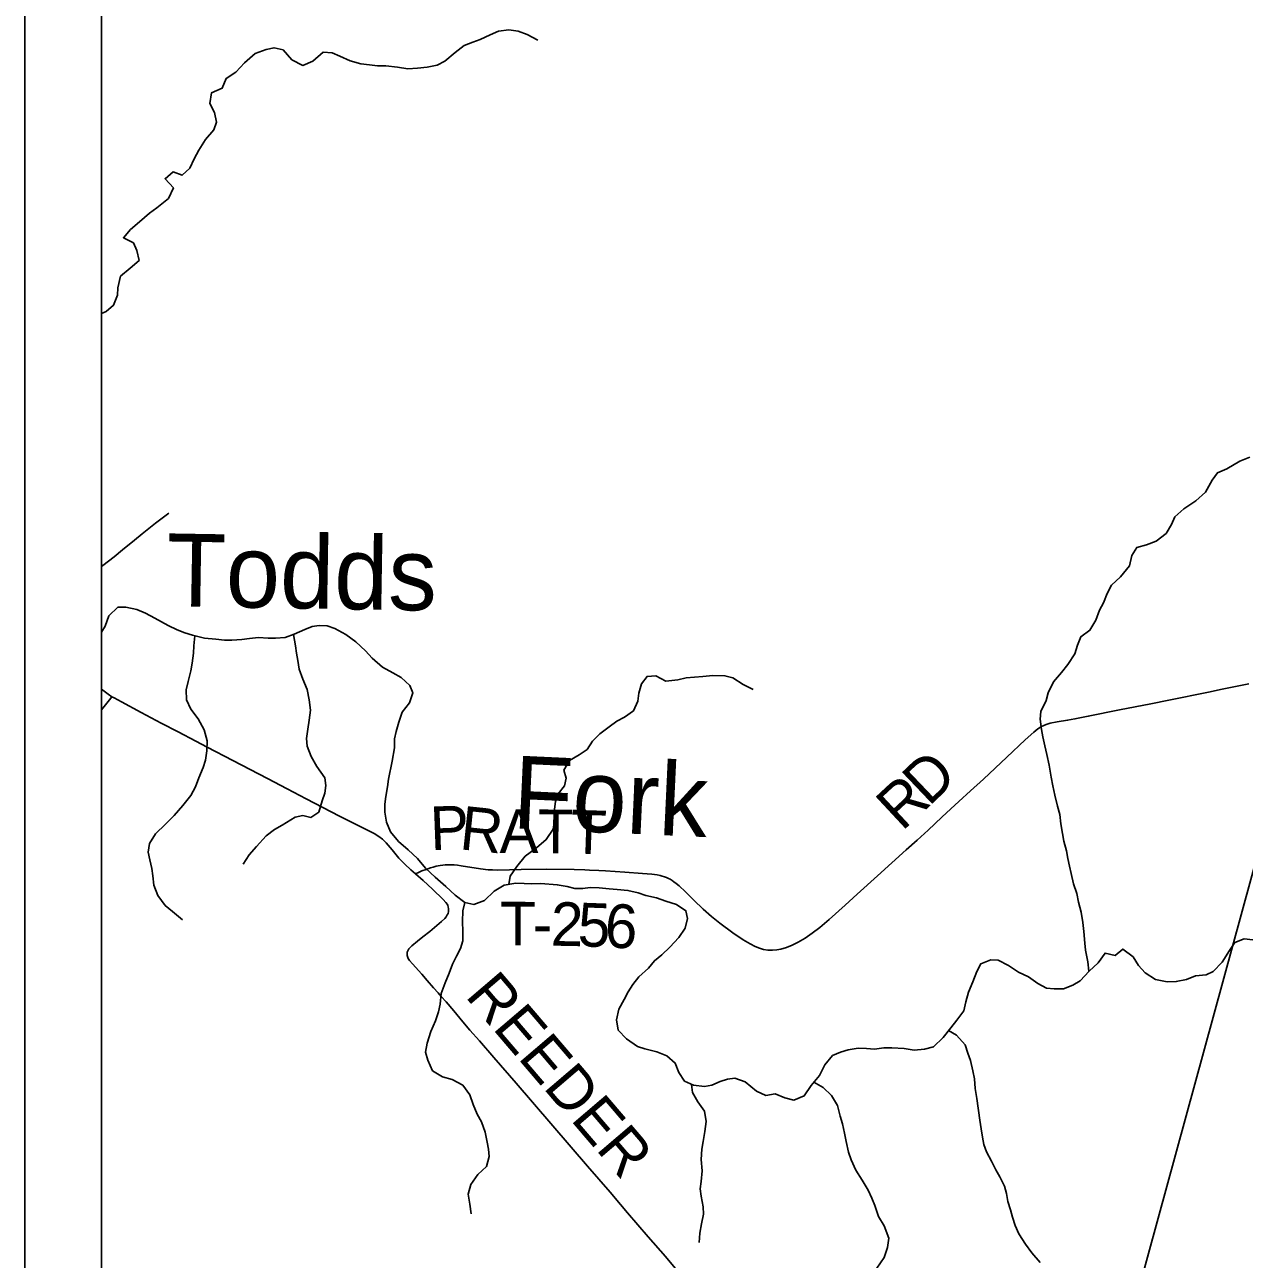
# Model space of a CAD drawing. Extents: x 0 to 34, y 0 to 22.
# Drawn here: x 2 to 3.586, y 15.761 to 17.368 of the extents above; entities that cross this region are included whole.
import ezdxf

# ---------------------------------------------------------------- set-up
doc = ezdxf.new("R2010")
doc.units = 0
for name, color, linetype in [('GM_X_Minor_River', 7, 'Continuous'), ('GM_X_Minor_River_Text', 7, 'Continuous'), ('GM_X_Township_Road', 7, 'Continuous'), ('GM_X_Township_Road_Text', 7, 'Continuous'), ('SH_Data', 7, 'Continuous')]:
    doc.layers.add(name, color=color, linetype=linetype)

msp = doc.modelspace()

# ---------------------------------------------------------------- linework, layer by layer
at = {"layer": 'GM_X_Minor_River'}
for points in [[(2.1, 16.9919), (2.1059, 16.9947), (2.1155, 17.0026), (2.1206, 17.0158), (2.1211, 17.0253), (2.1248, 17.0404), (2.137, 17.0509), (2.1489, 17.0609), (2.1457, 17.0739), (2.1413, 17.0838), (2.1285, 17.0905), (2.1378, 17.101), (2.1493, 17.1111), (2.1624, 17.1226), (2.1719, 17.1294), (2.1869, 17.1417), (2.1935, 17.1553), (2.1827, 17.1672), (2.1931, 17.1761), (2.2048, 17.1718), (2.2148, 17.1808), (2.2203, 17.1932), (2.2265, 17.2045), (2.235, 17.2181), (2.2462, 17.2308), (2.2494, 17.2407), (2.2469, 17.2536), (2.2406, 17.2651), (2.2431, 17.2791), (2.2569, 17.285), (2.262, 17.2978), (2.2746, 17.306), (2.2861, 17.318), (2.2996, 17.3303), (2.3141, 17.3355), (2.3244, 17.3376), (2.3361, 17.3348), (2.3476, 17.3221), (2.3619, 17.3147), (2.3749, 17.3202), (2.3883, 17.3318), (2.3997, 17.3309), (2.4099, 17.3269), (2.4234, 17.3207), (2.4374, 17.3167), (2.4484, 17.3154), (2.459, 17.3141), (2.4696, 17.314), (2.4848, 17.3123), (2.4984, 17.3102), (2.5109, 17.3111), (2.5234, 17.3125), (2.5367, 17.315), (2.5463, 17.3202), (2.5597, 17.3314), (2.5716, 17.3407), (2.5827, 17.3451), (2.5922, 17.3484), (2.6056, 17.3543), (2.6162, 17.3591), (2.6299, 17.3608), (2.642, 17.3591), (2.6537, 17.3548), (2.6673, 17.3474)], [(3.3843, 16.1362), (3.3828, 16.1486), (3.3799, 16.1634), (3.3789, 16.1729), (3.3776, 16.1878), (3.3763, 16.1996), (3.3742, 16.2129), (3.3706, 16.2262), (3.3685, 16.2372), (3.3641, 16.2498), (3.3613, 16.2632), (3.3588, 16.2727), (3.3567, 16.283), (3.3549, 16.2929), (3.3517, 16.3054), (3.3499, 16.3153), (3.3478, 16.3279), (3.3465, 16.34), (3.3432, 16.3511), (3.34, 16.3652), (3.3372, 16.3774), (3.3351, 16.3888), (3.3323, 16.4044), (3.3294, 16.4181), (3.3269, 16.4295), (3.3241, 16.4413), (3.3227, 16.4508), (3.321, 16.4642), (3.3215, 16.474), (3.3286, 16.4883), (3.3314, 16.4986), (3.338, 16.5129), (3.3484, 16.5249), (3.3569, 16.5354), (3.3658, 16.549), (3.3694, 16.5603), (3.3737, 16.5713), (3.3856, 16.5798), (3.393, 16.593), (3.3981, 16.6058), (3.4032, 16.6156), (3.4079, 16.6277), (3.4134, 16.6383), (3.4253, 16.6495), (3.4369, 16.6638), (3.4401, 16.677), (3.4467, 16.6876), (3.4589, 16.6908), (3.4715, 16.6956), (3.4845, 16.7056), (3.4915, 16.7173), (3.4958, 16.7275), (3.5077, 16.7376), (3.5234, 16.748), (3.5357, 16.7596), (3.5447, 16.7751), (3.5513, 16.7848), (3.5635, 16.79), (3.5803, 16.7996), (3.5936, 16.8048)], [(2.1, 16.5775), (2.1045, 16.5851), (2.1096, 16.5987), (2.1212, 16.6099), (2.1314, 16.6098), (2.1458, 16.6066), (2.1571, 16.6022), (2.1691, 16.5956), (2.1864, 16.5859), (2.1985, 16.5804), (2.2083, 16.5765), (2.2184, 16.5733), (2.2339, 16.5697), (2.2487, 16.5683), (2.2597, 16.5671), (2.2695, 16.5669), (2.2824, 16.5679), (2.2923, 16.5693), (2.3041, 16.5706), (2.3166, 16.5697), (2.3261, 16.5696), (2.3386, 16.5705), (2.3504, 16.5746), (2.3642, 16.5808), (2.3737, 16.5849), (2.3832, 16.5859), (2.3934, 16.5857), (2.4032, 16.5822), (2.4175, 16.5744), (2.4307, 16.5647), (2.4434, 16.5532), (2.452, 16.5436), (2.4654, 16.532), (2.479, 16.5242), (2.4895, 16.5184), (2.5011, 16.508), (2.5048, 16.4984), (2.5004, 16.4856), (2.4911, 16.4732), (2.4868, 16.4603), (2.4832, 16.4482), (2.4811, 16.4384), (2.481, 16.427), (2.4781, 16.4096), (2.4732, 16.3861), (2.4719, 16.3759), (2.4698, 16.3634), (2.4685, 16.3535), (2.4684, 16.3433), (2.4705, 16.3303), (2.4756, 16.3177), (2.486, 16.3051), (2.4988, 16.2943), (2.5107, 16.2827), (2.5215, 16.2704), (2.5339, 16.2585), (2.5477, 16.2465), (2.5601, 16.235), (2.5725, 16.2257), (2.5842, 16.2232), (2.5979, 16.228), (2.6106, 16.2404), (2.6236, 16.2481), (2.6388, 16.2506), (2.6498, 16.2504), (2.6596, 16.2499), (2.6714, 16.2505), (2.6926, 16.2487), (2.7055, 16.2463), (2.7157, 16.2439), (2.7259, 16.2437), (2.7354, 16.2451), (2.7472, 16.2449), (2.76, 16.2436), (2.7706, 16.2427), (2.7846, 16.2414), (2.7979, 16.2382), (2.8081, 16.2346), (2.8217, 16.2318), (2.8341, 16.2274), (2.8477, 16.2231), (2.8601, 16.2149), (2.8622, 16.205), (2.859, 16.1922), (2.8509, 16.1801), (2.8389, 16.1674), (2.8286, 16.1577), (2.819, 16.1498), (2.8112, 16.1401), (2.7989, 16.1288), (2.7908, 16.1191), (2.785, 16.1093)], [(2.2215, 16.5726), (2.2201, 16.5596), (2.2196, 16.5501), (2.2179, 16.5369), (2.2159, 16.527), (2.2126, 16.513), (2.2102, 16.5024), (2.2104, 16.4895), (2.2163, 16.4773), (2.2256, 16.4646), (2.2333, 16.4501), (2.2373, 16.436), (2.2367, 16.4231), (2.235, 16.411), (2.2323, 16.4011), (2.2267, 16.3876), (2.222, 16.3759), (2.2162, 16.3649), (2.2057, 16.3518), (2.1946, 16.3386), (2.183, 16.3274), (2.17, 16.3151), (2.1622, 16.3023), (2.1605, 16.2913), (2.1626, 16.281), (2.1655, 16.2699), (2.1665, 16.2601), (2.1678, 16.2483), (2.173, 16.2349), (2.1826, 16.2219), (2.1924, 16.2138), (2.2051, 16.203)], [(2.3498, 16.5744), (2.3521, 16.5597), (2.3535, 16.5498), (2.3552, 16.5403), (2.357, 16.5293), (2.3617, 16.5163), (2.3672, 16.5026), (2.37, 16.4893), (2.3717, 16.4759), (2.37, 16.4627), (2.3683, 16.4513), (2.3666, 16.4388), (2.3673, 16.4289), (2.3724, 16.4156), (2.3801, 16.4026), (2.3902, 16.388), (2.3915, 16.3777), (2.3903, 16.3679), (2.3871, 16.358), (2.3827, 16.3433), (2.372, 16.3362), (2.3618, 16.3386), (2.3519, 16.3365), (2.3347, 16.3261), (2.3247, 16.3205), (2.314, 16.3123), (2.3013, 16.2985), (2.292, 16.2876), (2.2843, 16.2755)], [(2.6295, 16.2491), (2.6314, 16.2598), (2.6399, 16.2726), (2.6511, 16.2857), (2.6656, 16.2969), (2.6783, 16.3074), (2.6872, 16.3209), (2.6897, 16.3346), (2.6891, 16.3471), (2.6904, 16.357), (2.694, 16.3668), (2.7021, 16.3773), (2.7041, 16.3875), (2.7012, 16.3978), (2.7086, 16.4102), (2.7212, 16.4177), (2.7316, 16.4247), (2.7386, 16.4353), (2.7482, 16.445), (2.7601, 16.454), (2.77, 16.4614), (2.78, 16.4666), (2.7918, 16.4748), (2.7977, 16.4876), (2.799, 16.4978), (2.8022, 16.5099), (2.8095, 16.5197), (2.8209, 16.5207), (2.8341, 16.5137), (2.8497, 16.5154), (2.8603, 16.5179), (2.8713, 16.5189), (2.882, 16.5195), (2.8949, 16.5208), (2.9108, 16.5206), (2.921, 16.5178), (2.9345, 16.5093), (2.9477, 16.5026)], [(2.5725, 16.2257), (2.57, 16.2147), (2.5695, 16.201), (2.57, 16.1878), (2.5698, 16.1756), (2.5667, 16.1658), (2.5616, 16.156), (2.5565, 16.1454), (2.5522, 16.1337), (2.5467, 16.1209), (2.5419, 16.1073), (2.5406, 16.0932), (2.5382, 16.0834), (2.5342, 16.0717), (2.5283, 16.0577), (2.5235, 16.0426), (2.5215, 16.0309), (2.5244, 16.0206), (2.5306, 16.0068), (2.5434, 15.9987), (2.5562, 15.9955), (2.5698, 15.9881), (2.5791, 15.9754), (2.5831, 15.9628), (2.5886, 15.9502), (2.5941, 15.9403), (2.5988, 15.9266), (2.6017, 15.914), (2.6034, 15.9045), (2.6041, 15.895), (2.6005, 15.8821), (2.5893, 15.8716), (2.5804, 15.8588), (2.5768, 15.846), (2.5789, 15.8331), (2.5806, 15.8205)], [(2.785, 16.1093), (2.7796, 16.0995), (2.7729, 16.0867), (2.7697, 16.073), (2.7718, 16.0597), (2.7826, 16.0482), (2.7969, 16.0381), (2.8067, 16.0353), (2.8222, 16.0313), (2.8354, 16.0262), (2.8462, 16.0166), (2.8506, 16.0044), (2.8584, 15.9933), (2.8701, 15.9878), (2.8841, 15.9864), (2.8936, 15.9878), (2.9046, 15.9926), (2.9142, 15.9959), (2.9237, 15.9969), (2.9369, 15.9922), (2.9519, 15.9802), (2.9639, 15.9744), (2.9761, 15.9765), (2.9885, 15.9714), (3.0002, 15.9685), (3.0139, 15.974), (3.0229, 15.9876), (3.0337, 16.0007), (3.0407, 16.0143), (3.0507, 16.0267), (3.061, 16.0307), (3.0709, 16.034), (3.0839, 16.0361), (3.0948, 16.0356), (3.1051, 16.0347), (3.1176, 16.0364), (3.1279, 16.0367), (3.1438, 16.0357), (3.157, 16.0336), (3.1703, 16.0346), (3.1821, 16.0378), (3.1948, 16.0498), (3.2044, 16.0626), (3.2126, 16.0727), (3.2214, 16.0847), (3.2239, 16.0965), (3.2275, 16.1089), (3.2334, 16.1225), (3.2385, 16.1358), (3.2436, 16.1456), (3.2565, 16.1511), (3.266, 16.1506), (3.2796, 16.1435), (3.2927, 16.135), (3.3055, 16.1288), (3.3179, 16.1202), (3.3292, 16.114), (3.339, 16.1131), (3.3512, 16.1133), (3.3634, 16.1181), (3.3729, 16.1237), (3.3845, 16.1364), (3.3964, 16.1473), (3.4053, 16.1597), (3.4185, 16.1568), (3.4285, 16.1651), (3.4416, 16.155), (3.4487, 16.1435), (3.4572, 16.1339), (3.4708, 16.1254), (3.4859, 16.1225), (3.4977, 16.1227), (3.511, 16.1256), (3.5228, 16.1304), (3.5365, 16.1317), (3.546, 16.1357), (3.5576, 16.1481), (3.5669, 16.1632), (3.5742, 16.1737), (3.5861, 16.1785), (3.5974, 16.1772)], [(3.2017, 16.059), (3.2119, 16.053), (3.2231, 16.0403), (3.2267, 16.0296), (3.23, 16.0201), (3.2332, 16.0064), (3.2353, 15.9961), (3.2363, 15.9835), (3.2384, 15.9706), (3.2425, 15.9425), (3.2442, 15.931), (3.246, 15.9204), (3.2474, 15.9109), (3.251, 15.9013), (3.2573, 15.8891), (3.2632, 15.878), (3.2684, 15.8685), (3.2743, 15.8566), (3.2768, 15.8471), (3.2789, 15.8368), (3.2821, 15.8258), (3.2847, 15.8162), (3.2883, 15.8052), (3.2931, 15.7945), (3.3016, 15.7811), (3.3098, 15.7696), (3.3206, 15.7573)], [(2.8674, 15.989), (2.8684, 15.9783), (2.8754, 15.9661), (2.8844, 15.9542), (2.8864, 15.9405), (2.8847, 15.9276), (2.8823, 15.9147), (2.8806, 15.9045), (2.88, 15.8912), (2.8813, 15.8764), (2.88, 15.8627), (2.8787, 15.8529), (2.8797, 15.8434), (2.8826, 15.8297), (2.8828, 15.8202), (2.8803, 15.8077), (2.8783, 15.7956), (2.8773, 15.7831)], [(3.0263, 15.9918), (3.0384, 15.9851), (3.0492, 15.9743), (3.057, 15.9613), (3.0606, 15.9476), (3.0635, 15.9377), (3.0663, 15.9255), (3.0684, 15.9145), (3.0717, 15.9008), (3.0749, 15.8908), (3.0812, 15.8775), (3.0893, 15.8644), (3.0971, 15.8514), (3.1019, 15.8411), (3.1059, 15.8312), (3.1106, 15.8171), (3.118, 15.8048), (3.1239, 15.7888), (3.1222, 15.7767), (3.1178, 15.7638), (3.1085, 15.7499)]]:
    msp.add_lwpolyline(points, dxfattribs=at)
at = {"layer": 'GM_X_Township_Road'}
for points in [[(3.7787, 17.0143), (3.7921, 17.074), (3.9903, 17.6899), (4.0744, 17.9948), (4.1901, 18.4135), (4.1943, 18.4289), (4.2897, 18.7747), (4.3389, 18.9527), (4.4789, 19.5742), (4.4849, 19.6021), (4.4654, 19.6041), (3.501, 19.6889), (3.4805, 19.8366), (3.1735, 19.8394), (3.1019, 19.912), (2.3144, 20.5665), (2.1, 20.7431), (2.1, 15.597), (2.2517, 15.5643), (3.1228, 15.3686), (3.3385, 15.3189), (3.6691, 16.5264), (3.7277, 16.7873)], [(3.7277, 16.7873), (3.6691, 16.5264), (3.3385, 15.3189), (3.2153, 14.8228), (3.0598, 14.2522), (3.3693, 14.1947), (3.882, 14.1), (5.5061, 14.1), (5.6307, 14.246), (5.7089, 14.3412), (6.2381, 14.9624), (6.7874, 15.6255), (6.8121, 15.6375), (7.6646, 16.0363), (8.8399, 16.5839), (8.8447, 16.5834), (8.8816, 16.5789), (8.8995, 16.5764), (8.9, 16.5763), (8.9, 19.1426)], [(2.1, 16.6627), (2.1016, 16.664), (2.1162, 16.6755), (2.1273, 16.6845), (2.1427, 16.6969), (2.1528, 16.7052), (2.1702, 16.7193), (2.1874, 16.7323)], [(2.1135, 16.4931), (2.1085, 16.4965), (2.1, 16.503)], [(2.5083, 16.263), (2.5121, 16.2646), (2.5167, 16.2666), (2.522, 16.2686), (2.5278, 16.2706), (2.5311, 16.2717), (2.535, 16.2727), (2.5376, 16.2733), (2.5405, 16.2739), (2.5437, 16.2743), (2.5471, 16.2746), (2.5523, 16.2747), (2.5586, 16.2745), (2.5629, 16.2741), (2.5678, 16.2734), (2.593, 16.2693), (2.6028, 16.2683), (2.6083, 16.2679), (2.6152, 16.2678), (2.6456, 16.2685), (2.6786, 16.2691), (2.7146, 16.2684), (2.7287, 16.2679), (2.7348, 16.2678), (2.7466, 16.2671), (2.7553, 16.2666), (2.7804, 16.2651), (2.8037, 16.2635), (2.8095, 16.2631), (2.8156, 16.2625), (2.8192, 16.262), (2.8225, 16.2615), (2.8264, 16.2607), (2.8291, 16.26), (2.8322, 16.2592), (2.8348, 16.2582), (2.8373, 16.257), (2.8396, 16.2559), (2.8423, 16.2542), (2.8444, 16.2526), (2.8473, 16.2505), (2.8511, 16.2474), (2.8593, 16.2396), (2.8704, 16.2286), (2.8823, 16.217), (2.8931, 16.2076), (2.9043, 16.1988), (2.9212, 16.1863), (2.9345, 16.1771), (2.9435, 16.1717), (2.9501, 16.1683), (2.9558, 16.166), (2.9611, 16.1645), (2.9665, 16.1637), (2.9727, 16.1636), (2.9782, 16.164), (2.9836, 16.1651), (2.9907, 16.1672), (2.9981, 16.1702), (3.0059, 16.1741), (3.015, 16.1794), (3.0242, 16.1857), (3.034, 16.1932), (3.0463, 16.2036), (3.0671, 16.2223), (3.0828, 16.2364), (3.109, 16.2601), (3.1463, 16.294), (3.1606, 16.3069), (3.1749, 16.3198), (3.193, 16.3367), (3.2044, 16.3473), (3.2148, 16.357), (3.23, 16.3708), (3.247, 16.3862), (3.2775, 16.4146), (3.3014, 16.4372), (3.3124, 16.4473), (3.3179, 16.4515), (3.3227, 16.4545), (3.3284, 16.4572), (3.3338, 16.4588), (3.343, 16.4605), (3.3564, 16.4628), (3.3659, 16.4645), (3.3833, 16.4679), (3.4241, 16.4761), (3.4649, 16.4842), (3.4881, 16.4888), (3.5398, 16.4993), (3.5575, 16.503), (3.5922, 16.5099)], [(2.1, 16.4764), (2.1101, 16.4891), (2.1135, 16.4931)], [(2.5083, 16.263), (2.5023, 16.2682), (2.4946, 16.2753), (2.4868, 16.2835), (2.4779, 16.2942), (2.4701, 16.3031), (2.4652, 16.3078), (2.4604, 16.3116), (2.4547, 16.3153), (2.4443, 16.3206), (2.4095, 16.3379), (2.3663, 16.3607), (2.3415, 16.3733), (2.316, 16.3868), (2.2706, 16.4103), (2.2373, 16.4277), (2.2225, 16.4356), (2.1997, 16.4476), (2.1776, 16.4589), (2.1517, 16.473), (2.126, 16.4865), (2.1211, 16.4891), (2.1162, 16.4917), (2.1135, 16.4931)], [(2.8482, 15.7474), (2.8333, 15.7649), (2.811, 15.7908), (2.7841, 15.8218), (2.7748, 15.8326), (2.7613, 15.8488), (2.732, 15.8827), (2.6393, 15.9906), (2.6103, 16.0239), (2.5917, 16.0455), (2.579, 16.0597), (2.57, 16.0703), (2.558, 16.0845), (2.548, 16.0963), (2.5418, 16.1032), (2.5378, 16.1079), (2.5319, 16.1147), (2.5235, 16.1242), (2.5166, 16.1323), (2.5042, 16.1459), (2.5006, 16.1501), (2.4989, 16.1528), (2.4983, 16.1539), (2.4979, 16.1552), (2.4975, 16.1565), (2.4973, 16.1581), (2.4974, 16.1597), (2.4976, 16.1612), (2.4982, 16.1628), (2.4998, 16.1652), (2.5012, 16.1671), (2.5036, 16.1692), (2.511, 16.1751), (2.5179, 16.1809), (2.5269, 16.188), (2.5421, 16.2007), (2.5466, 16.2049), (2.548, 16.2068), (2.5497, 16.2094), (2.5506, 16.2114), (2.5511, 16.2139), (2.5511, 16.2172), (2.5508, 16.2201), (2.5503, 16.2216), (2.5498, 16.2228), (2.5477, 16.2256), (2.5443, 16.2294), (2.5303, 16.2428), (2.5183, 16.2542), (2.5083, 16.263)]]:
    msp.add_lwpolyline(points, dxfattribs=at)
at = {"layer": 'SH_Data'}
for p, q in [((2, 21), (2, 14)), ((2.1, 20.9), (2.1, 14.1))]:
    msp.add_line(p, q, dxfattribs=at)

# ---------------------------------------------------------------- texts
at = {"layer": 'GM_X_Minor_River_Text'}
for s, rotation, p in [('Todds', 359.0438, (2.1837, 16.6112)), ('Fork', 357.349, (2.6335, 16.3223))]:
    msp.add_text(s, height=0.09469, rotation=rotation, dxfattribs=at).set_placement(p)
at = {"layer": 'GM_X_Township_Road_Text'}
for s, height, rotation, p in [('D', 0.0568, 43.6043, (3.1758, 16.3497)), ('R', 0.0568, 42.9269, (3.1411, 16.3174)), ('P', 0.0568, 2.1291, (2.5282, 16.2935)), ('R', 0.0568, 353.9626, (2.5644, 16.295)), ('A', 0.0568, 0.1952, (2.6175, 16.2898)), ('T', 0.0568, 359.5971, (2.6674, 16.2899)), ('T', 0.0568, 358.1311, (2.7095, 16.2896)), ('T', 0.0568, 359.9571, (2.6184, 16.1697)), ('2', 0.0568, 358.8551, (2.6839, 16.1695)), ('5', 0.0568, 357.944, (2.7187, 16.1688)), ('6', 0.0568, 357.194, (2.7535, 16.1675)), ('-', 0.0568, 359.6331, (2.6608, 16.1696)), ('REEDER', 0.05682, 310.5057, (2.5718, 16.1037))]:
    msp.add_text(s, height=height, rotation=rotation, dxfattribs=at).set_placement(p)

doc.saveas('drawing.dxf')
